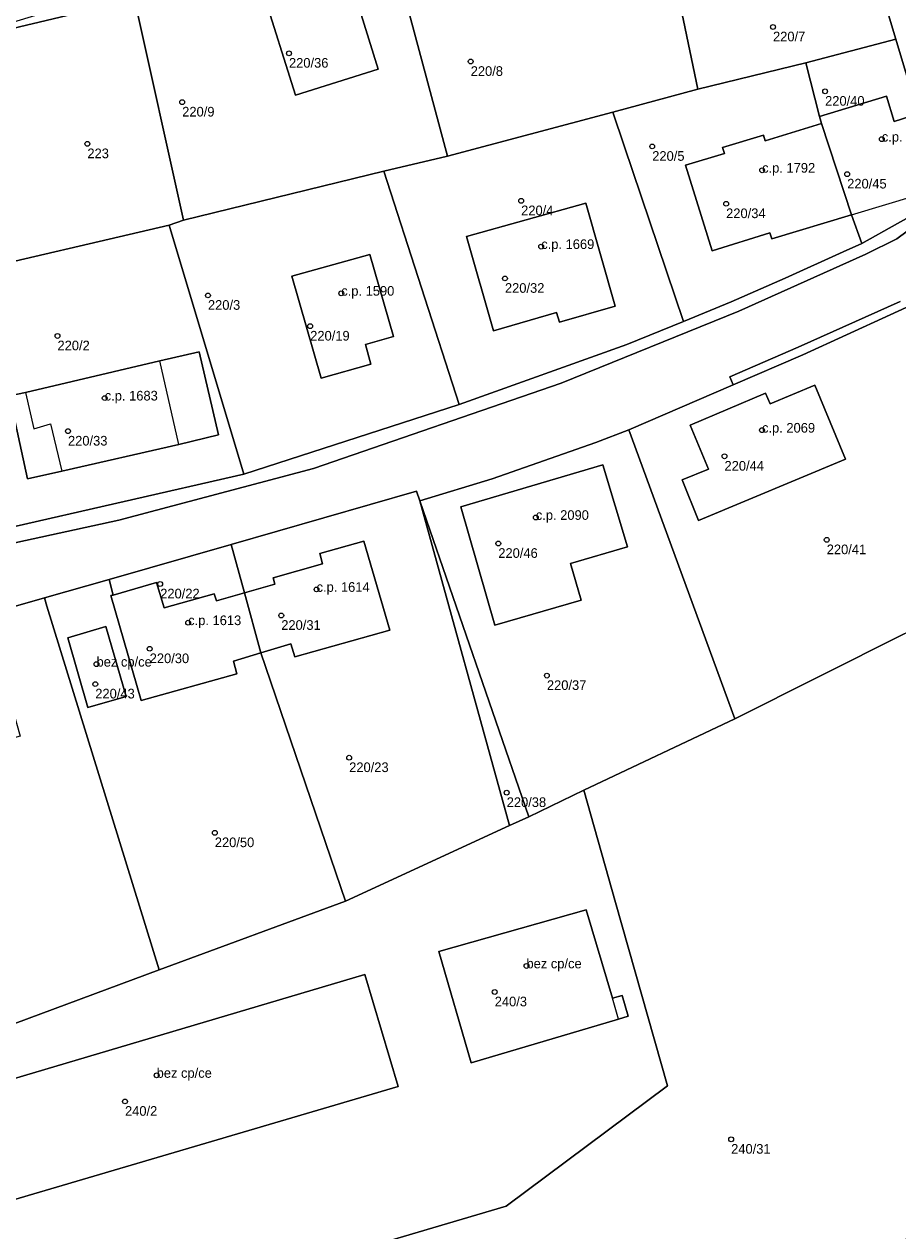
# Model space of a CAD drawing. Extents: x -878211 to -870363, y -1058464 to -1052522.
# Drawn here: x -874142 to -874051.4, y -1056111.9 to -1055986.8 of the extents above; entities that cross this region are included whole.
import ezdxf

# ---------------------------------------------------------------- set-up
doc = ezdxf.new("R2010")
doc.units = 0
for name, color, linetype in [('Vrstva 50', 7, 'Continuous'), ('Vrstva 51', 7, 'Continuous'), ('Vrstva 52', 7, 'Continuous')]:
    doc.layers.add(name, color=color, linetype=linetype)

msp = doc.modelspace()

# ---------------------------------------------------------------- linework, layer by layer
at = {"layer": 'Vrstva 50'}
for centre in [(-874064.38, -1055987.13994), (-874114.56, -1055989.86994), (-874095.72, -1055990.71994), (-874058.98, -1055993.80994), (-874125.63, -1055994.92994), (-874135.46, -1055999.24994), (-874053.1, -1055998.76994), (-874076.9, -1055999.51994), (-874065.51, -1056001.98994), (-874056.69, -1056002.38994), (-874090.49, -1056005.15994), (-874069.24, -1056005.45994), (-874088.41, -1056009.89994), (-874092.17, -1056013.19994), (-874122.96, -1056014.95994), (-874109.14, -1056014.73994), (-874138.56, -1056019.15994), (-874112.36, -1056018.14994), (-874133.66, -1056025.59994), (-874137.47, -1056029.02994), (-874065.52, -1056028.92994), (-874069.41, -1056031.62994), (-874088.97, -1056037.96994), (-874058.81, -1056040.28994), (-874092.86, -1056040.66994), (-874127.91, -1056044.86994), (-874111.7, -1056045.42994), (-874125.01, -1056048.87994), (-874115.36, -1056048.12994), (-874129, -1056051.57994), (-874134.51, -1056053.17994), (-874134.64, -1056055.23994), (-874087.82, -1056054.35994), (-874108.32, -1056062.86994), (-874091.99, -1056066.48994), (-874122.25, -1056070.64994), (-874089.94, -1056084.44994), (-874093.23, -1056087.14994), (-874128.28, -1056095.78994), (-874131.56, -1056098.48994), (-874068.72, -1056102.41994)]:
    msp.add_circle(centre, 0.25, dxfattribs=at)
at = {"layer": 'Vrstva 51'}
for points in [[(-874039.26, -1055960.99), (-874053.99, -1055954.45), (-874058.59, -1055953.79), (-874062.33, -1055954.49), (-874091.53, -1055969.3), (-874122.59, -1055980.36), (-874150.97, -1055989.01), (-874158.79, -1055991.05), (-874151.7, -1055989.31), (-874130.58, -1055984.27), (-874104.9, -1055975.23), (-874095.92, -1055972.47), (-874089.47, -1055971), (-874078.43, -1055966.08), (-874061.46, -1055955.78), (-874038.62, -1055964.71)], [(-874143.78, -1056040.76), (-874132.19, -1056038.24), (-874112.02, -1056032.88), (-874086.33, -1056024.06), (-874067.92, -1056016.59), (-874054.77, -1056010.67), (-874051.56, -1056009.11), (-874037.13, -1055998.43)], [(-874037.13, -1055998.43), (-874051.56, -1056009.11), (-874054.77, -1056010.67), (-874067.92, -1056016.59), (-874086.33, -1056024.06), (-874112.02, -1056032.88), (-874132.19, -1056038.24), (-874143.78, -1056040.76)], [(-874048.75, -1056006), (-874051.48, -1056007.49), (-874055.18, -1056009.57), (-874057.09, -1056010.44), (-874063.13, -1056013.18), (-874068.71, -1056015.62), (-874073.66, -1056017.67), (-874079.52, -1056020.04), (-874096.92, -1056026.27), (-874119.24, -1056033.48), (-874144.04, -1056039.16)], [(-874051.21, -1056015.58), (-874061.78, -1056020.31), (-874068.87, -1056023.39), (-874068.51, -1056024.22), (-874061.28, -1056021.1), (-874043.19, -1056012.81)], [(-874158.85, -1056051.74), (-874139.91, -1056046.31), (-874133.21, -1056044.39), (-874120.56, -1056040.76), (-874101.35, -1056035.25), (-874101.01, -1056036.26), (-874093.51, -1056033.97), (-874082.74, -1056030.19), (-874079.34, -1056028.88), (-874068.51, -1056024.22), (-874068.87, -1056023.39), (-874061.78, -1056020.31), (-874051.21, -1056015.58)], [(-874118.47, -1056117.14), (-874092.05, -1056109.34), (-874075.33, -1056096.89), (-874080.7, -1056077.88), (-874083.99, -1056066.24), (-874089.71, -1056068.99), (-874091.71, -1056069.91), (-874108.7, -1056077.73), (-874128.02, -1056084.85), (-874142.98, -1056090.4), (-874146.75, -1056091.8), (-874167.24, -1056095.36), (-874209.15, -1056102.64), (-874215.93, -1056103.82), (-874220.34, -1056110.44), (-874220.26, -1056114.81)]]:
    msp.add_lwpolyline(points, dxfattribs=at)
for points in [[(-874061.46, -1055955.78), (-874078.43, -1055966.08), (-874076.97, -1055970.76), (-874073.03, -1055969.93), (-874072.64, -1055971.8), (-874066.64, -1055970.52), (-874064.5, -1055980.27), (-874074.5, -1055982.46), (-874072.17, -1055993.59), (-874060.99, -1055990.85), (-874051.65, -1055988.42)], [(-874032.66, -1055981.61), (-874033.78, -1055973.82), (-874038.62, -1055964.71), (-874061.46, -1055955.78), (-874051.65, -1055988.42), (-874049.34, -1055996.14), (-874046.98, -1056003.51), (-874046.78, -1056004.18), (-874038.26, -1055997.34), (-874034.3, -1055989.51)], [(-874095.92, -1055972.47), (-874104.9, -1055975.23), (-874098.11, -1056000.54), (-874081, -1055995.96), (-874072.17, -1055993.59), (-874074.5, -1055982.46), (-874084.39, -1055984.6), (-874086.47, -1055974.86), (-874080.27, -1055973.53), (-874080.69, -1055971.59), (-874076.97, -1055970.76), (-874078.43, -1055966.08), (-874089.47, -1055971)], [(-874125.51, -1056007.16), (-874104.71, -1056002.08), (-874098.11, -1056000.54), (-874104.9, -1055975.23), (-874130.58, -1055984.27)], [(-874117.29, -1055983.34), (-874113.9, -1055994.21), (-874105.32, -1055991.52), (-874108.71, -1055980.6)], [(-874117.29, -1055983.34), (-874108.71, -1055980.6), (-874105.32, -1055991.52), (-874113.9, -1055994.21)], [(-874158.79, -1055991.05), (-874149.24, -1056012.87), (-874126.98, -1056007.69), (-874125.51, -1056007.16), (-874130.58, -1055984.27), (-874151.7, -1055989.31)], [(-874059.55, -1055996.42), (-874052.61, -1055994.31), (-874051.81, -1055996.92), (-874049.34, -1055996.14), (-874051.65, -1055988.42), (-874060.99, -1055990.85)], [(-874070.69, -1056010.33), (-874073.45, -1056001.47), (-874069.42, -1056000.25), (-874069.63, -1055999.62), (-874065.37, -1055998.34), (-874065.19, -1055998.95), (-874059.34, -1055997.15), (-874059.55, -1055996.42), (-874060.99, -1055990.85), (-874072.17, -1055993.59), (-874081, -1055995.96), (-874079.82, -1055999.45), (-874073.66, -1056017.67), (-874068.71, -1056015.62), (-874063.13, -1056013.18), (-874057.09, -1056010.44), (-874055.18, -1056009.57), (-874056.25, -1056006.62), (-874064.5, -1056009.11), (-874064.71, -1056008.48)], [(-874046.78, -1056004.18), (-874046.98, -1056003.51), (-874049.34, -1055996.14), (-874051.81, -1055996.92), (-874052.61, -1055994.31), (-874059.55, -1055996.42), (-874059.34, -1055997.15), (-874056.25, -1056006.62), (-874055.18, -1056009.57), (-874051.48, -1056007.49), (-874048.75, -1056006)], [(-874079.82, -1055999.45), (-874081, -1055995.96), (-874098.11, -1056000.54), (-874104.71, -1056002.08), (-874096.92, -1056026.27), (-874079.52, -1056020.04), (-874073.66, -1056017.67)], [(-874059.34, -1055997.15), (-874065.19, -1055998.95), (-874065.37, -1055998.34), (-874069.63, -1055999.62), (-874069.42, -1056000.25), (-874073.45, -1056001.47), (-874070.69, -1056010.33), (-874064.71, -1056008.48), (-874064.5, -1056009.11), (-874056.25, -1056006.62)], [(-874104.71, -1056002.08), (-874125.51, -1056007.16), (-874126.98, -1056007.69), (-874119.24, -1056033.48), (-874096.92, -1056026.27)], [(-874093.35, -1056018.64), (-874096.17, -1056008.87), (-874083.8, -1056005.4), (-874080.73, -1056016.08), (-874086.51, -1056017.72), (-874086.81, -1056016.74)], [(-874093.35, -1056018.64), (-874086.81, -1056016.74), (-874086.51, -1056017.72), (-874080.73, -1056016.08), (-874083.8, -1056005.4), (-874096.17, -1056008.87)], [(-874119.24, -1056033.48), (-874126.98, -1056007.69), (-874149.24, -1056012.87), (-874144.04, -1056039.16)], [(-874111.24, -1056023.53), (-874106.06, -1056022.09), (-874106.64, -1056020.04), (-874103.71, -1056019.21), (-874106.17, -1056010.73), (-874114.26, -1056012.97)], [(-874111.24, -1056023.53), (-874114.26, -1056012.97), (-874106.17, -1056010.73), (-874103.71, -1056019.21), (-874106.64, -1056020.04), (-874106.06, -1056022.09)], [(-874068.51, -1056024.22), (-874079.34, -1056028.88), (-874068.35, -1056058.84), (-874050.77, -1056050.02), (-874041.39, -1056045.32), (-874035.88, -1056038.23), (-874038.62, -1056028.71), (-874043.19, -1056012.81), (-874061.28, -1056021.1)], [(-874138.1, -1056033.19), (-874141.68, -1056033.96), (-874143.52, -1056025.35), (-874141.87, -1056025.03), (-874127.95, -1056021.74), (-874123.87, -1056020.79), (-874121.87, -1056029.41), (-874125.98, -1056030.4)], [(-874138.1, -1056033.19), (-874125.98, -1056030.4), (-874121.87, -1056029.41), (-874123.87, -1056020.79), (-874127.95, -1056021.74), (-874141.87, -1056025.03), (-874143.52, -1056025.35), (-874141.68, -1056033.96)], [(-874064.69, -1056026.2), (-874065.16, -1056025.09), (-874072.97, -1056028.39), (-874071.06, -1056032.98), (-874073.8, -1056034.07), (-874072.12, -1056038.28), (-874056.85, -1056031.94), (-874060.06, -1056024.27)], [(-874064.69, -1056026.2), (-874060.06, -1056024.27), (-874056.85, -1056031.94), (-874072.12, -1056038.28), (-874073.8, -1056034.07), (-874071.06, -1056032.98), (-874072.97, -1056028.39), (-874065.16, -1056025.09)], [(-874101.01, -1056036.26), (-874089.71, -1056068.99), (-874083.99, -1056066.24), (-874068.35, -1056058.84), (-874079.34, -1056028.88), (-874082.74, -1056030.19), (-874093.51, -1056033.97)], [(-874084.28, -1056046.53), (-874085.39, -1056042.74), (-874079.48, -1056041.01), (-874082.02, -1056032.52), (-874096.75, -1056036.87), (-874093.23, -1056049.15)], [(-874084.28, -1056046.53), (-874093.23, -1056049.15), (-874096.75, -1056036.87), (-874082.02, -1056032.52), (-874079.48, -1056041.01), (-874085.39, -1056042.74)], [(-874120.28, -1056041.79), (-874119.18, -1056045.79), (-874116.02, -1056044.9), (-874116.19, -1056044.23), (-874111.1, -1056042.77), (-874111.35, -1056041.69), (-874106.79, -1056040.42), (-874104.12, -1056049.65), (-874113.97, -1056052.43), (-874114.36, -1056051.06), (-874117.47, -1056052), (-874108.7, -1056077.73), (-874091.71, -1056069.91), (-874101.01, -1056036.26), (-874101.35, -1056035.25), (-874120.56, -1056040.76)], [(-874083.99, -1056066.24), (-874080.7, -1056077.88), (-874075.33, -1056096.89), (-874092.05, -1056109.34), (-874118.47, -1056117.14), (-874116.81, -1056122.76), (-874101.89, -1056134.11), (-874098.83, -1056136.48), (-874062.01, -1056135.86), (-874057.99, -1056135.83), (-874048.77, -1056107.25), (-874039.57, -1056083.57), (-874003.01, -1056035.73), (-874020.49, -1056040.6), (-874041.66, -1056047.24), (-874050.77, -1056050.02), (-874068.35, -1056058.84)], [(-874091.71, -1056069.91), (-874089.71, -1056068.99), (-874101.01, -1056036.26)], [(-874127.49, -1056047.35), (-874122.33, -1056045.88), (-874122.09, -1056046.6), (-874119.18, -1056045.79), (-874120.28, -1056041.79), (-874120.56, -1056040.76), (-874133.21, -1056044.39), (-874132.79, -1056046.01), (-874128.29, -1056044.72)], [(-874117.47, -1056052), (-874114.36, -1056051.06), (-874113.97, -1056052.43), (-874104.12, -1056049.65), (-874106.79, -1056040.42), (-874111.35, -1056041.69), (-874111.1, -1056042.77), (-874116.19, -1056044.23), (-874116.02, -1056044.9), (-874119.18, -1056045.79)], [(-874139.91, -1056046.31), (-874139.65, -1056047.16), (-874128.02, -1056084.85), (-874108.7, -1056077.73), (-874117.47, -1056052), (-874120.32, -1056052.86), (-874119.98, -1056054.18), (-874129.87, -1056056.95), (-874133.02, -1056046.07), (-874132.79, -1056046.01), (-874133.21, -1056044.39)], [(-874119.98, -1056054.18), (-874120.32, -1056052.86), (-874117.47, -1056052), (-874119.18, -1056045.79), (-874122.09, -1056046.6), (-874122.33, -1056045.88), (-874127.49, -1056047.35), (-874128.29, -1056044.72), (-874132.79, -1056046.01), (-874133.02, -1056046.07), (-874129.87, -1056056.95)], [(-874139.65, -1056047.16), (-874139.91, -1056046.31), (-874158.85, -1056051.74), (-874158.61, -1056052.59), (-874157.51, -1056056.44), (-874154.58, -1056055.6), (-874154.74, -1056055.05), (-874149.54, -1056053.55), (-874149.81, -1056052.47), (-874145.12, -1056051.21), (-874142.44, -1056060.62), (-874152.57, -1056063.38), (-874152.93, -1056062.13), (-874155.92, -1056062.95), (-874146.98, -1056091.09), (-874146.75, -1056091.8), (-874142.98, -1056090.4), (-874128.02, -1056084.85)], [(-874137.48, -1056050.44), (-874133.54, -1056049.27), (-874131.44, -1056056.52), (-874135.4, -1056057.67)], [(-874137.48, -1056050.44), (-874135.4, -1056057.67), (-874131.44, -1056056.52), (-874133.54, -1056049.27)], [(-874095.68, -1056094.48), (-874080.4, -1056089.95), (-874079.4, -1056089.66), (-874080.02, -1056087.52), (-874081.01, -1056087.8), (-874083.75, -1056078.65), (-874099.04, -1056082.94)], [(-874095.68, -1056094.48), (-874099.04, -1056082.94), (-874083.75, -1056078.65), (-874081.01, -1056087.8), (-874080.02, -1056087.52), (-874079.4, -1056089.66), (-874080.4, -1056089.95)], [(-874147.62, -1056110.01), (-874103.25, -1056096.94), (-874106.68, -1056085.32), (-874150.96, -1056098.48)], [(-874147.62, -1056110.01), (-874150.96, -1056098.48), (-874106.68, -1056085.32), (-874103.25, -1056096.94)]]:
    msp.add_lwpolyline(points, close=True, dxfattribs=at)
at = {"layer": 'Vrstva 52'}
for points in [[(-874108.71, -1055980.6), (-874117.29, -1055983.34), (-874113.9, -1055994.21), (-874105.32, -1055991.52)], [(-874052.61, -1055994.31), (-874059.55, -1055996.42), (-874059.34, -1055997.15), (-874056.25, -1056006.62), (-874049.48, -1056004.57), (-874049.57, -1056004.28), (-874046.98, -1056003.51), (-874049.34, -1055996.14), (-874051.81, -1055996.92)], [(-874069.42, -1056000.25), (-874073.45, -1056001.47), (-874070.69, -1056010.33), (-874064.71, -1056008.48), (-874064.5, -1056009.11), (-874056.25, -1056006.62), (-874059.34, -1055997.15), (-874065.19, -1055998.95), (-874065.37, -1055998.34), (-874069.63, -1055999.62)], [(-874080.73, -1056016.08), (-874083.8, -1056005.4), (-874096.17, -1056008.87), (-874093.35, -1056018.64), (-874086.81, -1056016.74), (-874086.51, -1056017.72)], [(-874106.17, -1056010.73), (-874114.26, -1056012.97), (-874111.24, -1056023.53), (-874106.06, -1056022.09), (-874106.64, -1056020.04), (-874103.71, -1056019.21)], [(-874127.95, -1056021.74), (-874141.87, -1056025.03), (-874141.01, -1056028.79), (-874139.29, -1056028.28), (-874138.1, -1056033.19), (-874125.98, -1056030.4)], [(-874073.8, -1056034.07), (-874072.12, -1056038.28), (-874056.85, -1056031.94), (-874060.06, -1056024.27), (-874064.69, -1056026.2), (-874065.16, -1056025.09), (-874072.97, -1056028.39), (-874071.06, -1056032.98)], [(-874084.28, -1056046.53), (-874085.39, -1056042.74), (-874079.48, -1056041.01), (-874082.02, -1056032.52), (-874096.75, -1056036.87), (-874093.23, -1056049.15)], [(-874119.18, -1056045.79), (-874117.47, -1056052), (-874114.36, -1056051.06), (-874113.97, -1056052.43), (-874104.12, -1056049.65), (-874106.79, -1056040.42), (-874111.35, -1056041.69), (-874111.1, -1056042.77), (-874116.19, -1056044.23), (-874116.02, -1056044.9)], [(-874133.02, -1056046.07), (-874129.87, -1056056.95), (-874119.98, -1056054.18), (-874120.32, -1056052.86), (-874117.47, -1056052), (-874119.18, -1056045.79), (-874122.09, -1056046.6), (-874122.33, -1056045.88), (-874127.49, -1056047.35), (-874128.29, -1056044.72), (-874132.79, -1056046.01)], [(-874137.48, -1056050.44), (-874135.4, -1056057.67), (-874131.44, -1056056.52), (-874133.54, -1056049.27)], [(-874099.04, -1056082.94), (-874095.68, -1056094.48), (-874080.4, -1056089.95), (-874081.01, -1056087.8), (-874083.75, -1056078.65)], [(-874150.96, -1056098.48), (-874147.62, -1056110.01), (-874103.25, -1056096.94), (-874106.68, -1056085.32)]]:
    msp.add_lwpolyline(points, close=True, dxfattribs=at)

# ---------------------------------------------------------------- texts
at = {"layer": 'Vrstva 50'}
for s, p in [('220/7', (-874064.38, -1055988.629)), ('220/36', (-874114.56, -1055991.359)), ('220/8', (-874095.72, -1055992.209)), ('220/40', (-874058.98, -1055995.299)), ('220/9', (-874125.63, -1055996.419)), ('c.p. 2096', (-874053.1, -1055999.02)), ('223', (-874135.46, -1056000.739)), ('220/5', (-874076.9, -1056001.009)), ('c.p. 1792', (-874065.51, -1056002.24)), ('220/45', (-874056.69, -1056003.879)), ('220/4', (-874090.49, -1056006.649)), ('220/34', (-874069.24, -1056006.949)), ('c.p. 1669', (-874088.41, -1056010.149)), ('c.p. 1590', (-874109.14, -1056014.99)), ('220/32', (-874092.17, -1056014.689)), ('220/3', (-874122.96, -1056016.449)), ('220/19', (-874112.36, -1056019.639)), ('220/2', (-874138.56, -1056020.649)), ('c.p. 1683', (-874133.66, -1056025.85)), ('c.p. 2069', (-874065.52, -1056029.179)), ('220/33', (-874137.47, -1056030.519)), ('220/44', (-874069.41, -1056033.119)), ('c.p. 2090', (-874088.97, -1056038.22)), ('220/46', (-874092.86, -1056042.159)), ('220/41', (-874058.81, -1056041.779)), ('c.p. 1614', (-874111.7, -1056045.679)), ('220/22', (-874127.91, -1056046.359)), ('c.p. 1613', (-874125.01, -1056049.129)), ('220/31', (-874115.36, -1056049.619)), ('bez cp/ce', (-874134.51, -1056053.429)), ('220/30', (-874129, -1056053.069)), ('220/37', (-874087.82, -1056055.849)), ('220/43', (-874134.64, -1056056.729)), ('220/23', (-874108.32, -1056064.359)), ('220/38', (-874091.99, -1056067.979)), ('220/50', (-874122.25, -1056072.139)), ('bez cp/ce', (-874089.94, -1056084.7)), ('240/3', (-874093.23, -1056088.639)), ('bez cp/ce', (-874128.28, -1056096.04)), ('240/2', (-874131.56, -1056099.979)), ('240/31', (-874068.72, -1056103.909))]:
    msp.add_text(s, height=0.999996, dxfattribs=at).set_placement(p)

doc.saveas('drawing.dxf')
